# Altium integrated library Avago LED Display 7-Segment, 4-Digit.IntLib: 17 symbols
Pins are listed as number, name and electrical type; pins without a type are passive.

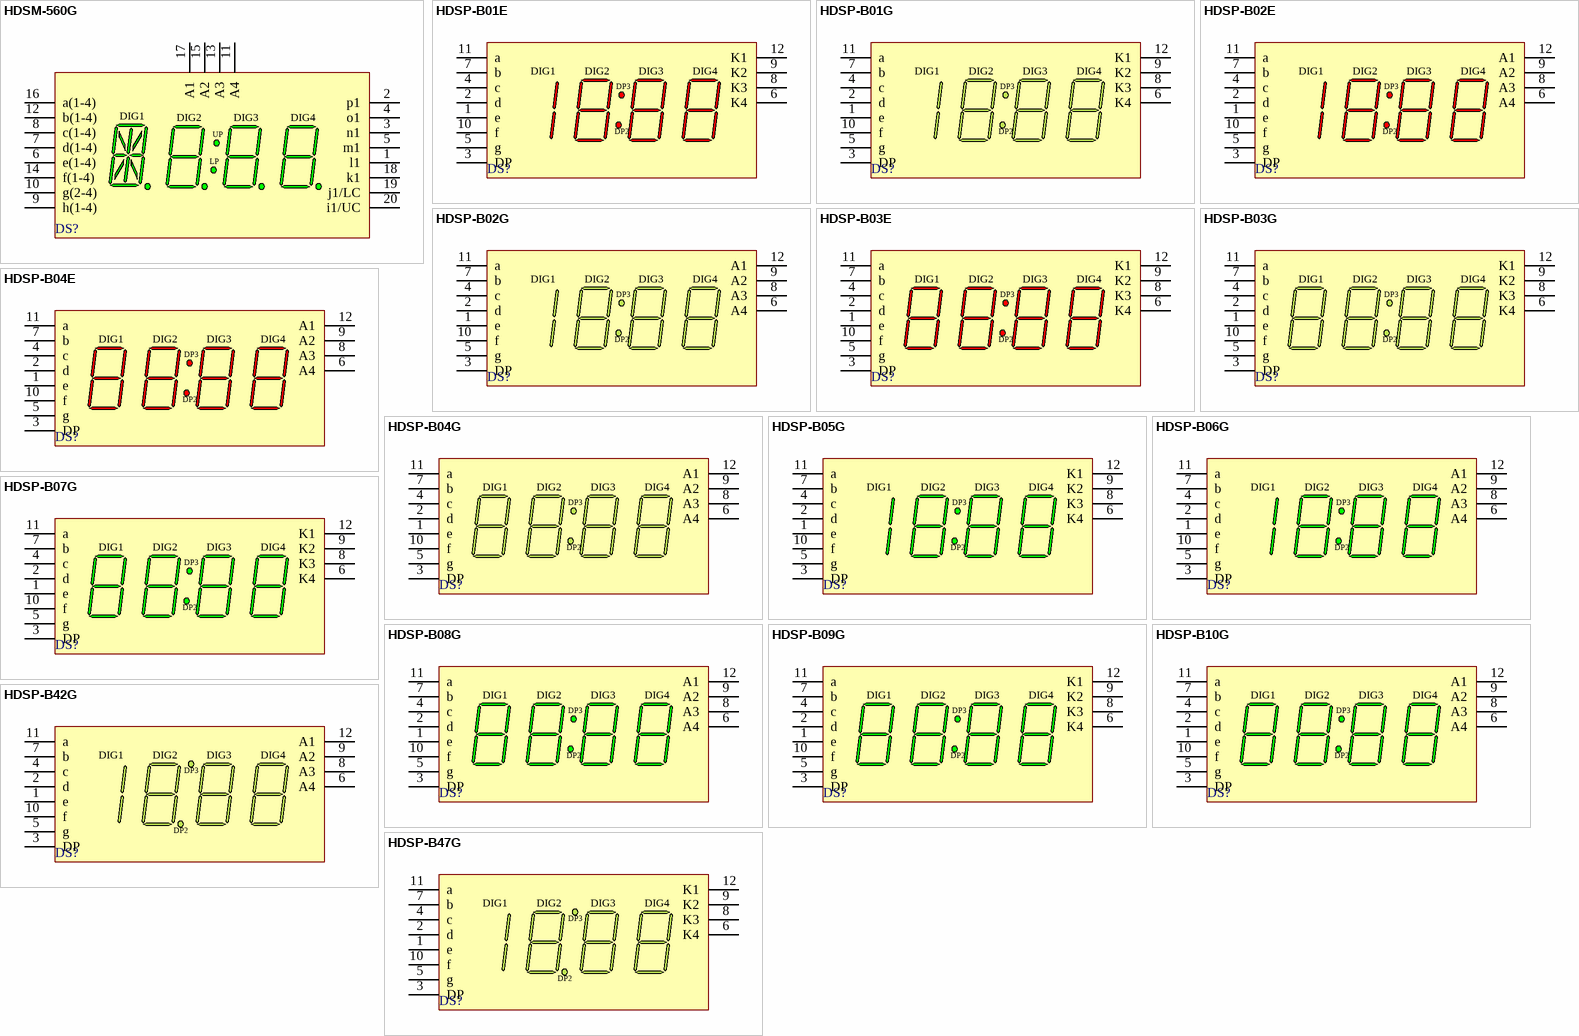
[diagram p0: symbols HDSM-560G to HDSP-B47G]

## HDSM-560G
designator DS?
8.9 mm Black Suface GAP Green 7-Segment Display: 4-Digit, CA; LuminousIntensity: 1250 ucd (Minimum).
footprint HDSM-560 (LED, 7-Segment Display, 8.9 mm, Four Digit; 20 Leads; Row Space 12 mm; Pitch 2.54 mm)
simulation model HDSM_560G (SUBCKT)
pins: 1 l1 "Digit 1 l Cathode", 2 p1 "Digit 1 p Cathode", 3 n1 "Digit 1 n Cathode", 4 o1 "Digit 1 o Cathode", 5 m1 "Digit 1 m Cathode", 6 e(1-4) "Digits (1-4) e Cathode", 7 d(1-4) "Digits (1-4) d Cathode", 8 c(1-4) "Digits (1-4) c Cathode", 9 h(1-4) "Digits (1-4) DP Cathode", 10 g(2-4) "Digits (2-4) g Cathode", 11 A4 "Digit 4 Common Anode", 12 b(1-4) "Digits (1-4) b Cathode", 13 A3 "Digit 3 Common Anode", 14 f(1-4) "Digits (1-4) f Cathode", 15 A2 "Digit 2 Common Anode", 16 a(1-4) "Digits (1-4) a Cathode", 17 A1 "Digit 1 Common Anode", 18 k1 "Digit 1 k Cathode", 19 j1/LC "Digit 1 j, LC Cathode", 20 i1/UC "Digit 1 i, UC Cathode"

## HDSP-B01E
designator DS?
14.22 mm GaP HER, Untinted, 18:88 4-Digit 7-Segment Display: CC, Gray Surface; LuminousIntensity: 3200 ucd (Minimum).; LED_Colour: High Efficiency Red (HER)
footprint B-18 (LED, 7-Segment Display, 14.22 mm, Four Digit, 18:88; 12 Leads; Row Space 15.24 mm; Pitch 2.54 mm)
simulation model HDSP_B01E (SUBCKT)
pins: 1 e "Digits (2-4) e Anode", 2 d "Digits (2-4) d Anode", 3 DP "Digits (2,3) DP Anode", 4 c "Digits (1-4) c Anode", 5 g "Digits (2-4) g Anode", 6 K4 "Digit 4 Common Cathode", 7 b "Digits (1-4) b Anode", 8 K3 "Digit 3 Common Cathode", 9 K2 "Digit 2 Common Cathode", 10 f "Digits (2-4) f Anode", 11 a "Digits (2-4) a Anode", 12 K1 "Digit 1 Common Cathode"

## HDSP-B01G
designator DS?
14.22 mm Tinted Green, 18:88 4-Digit 7-Segment Display: CC, Gray Surface; LuminousIntensity: 2000 ucd (Minimum).
footprint B-18 (LED, 7-Segment Display, 14.22 mm, Four Digit, 18:88; 12 Leads; Row Space 15.24 mm; Pitch 2.54 mm)
simulation model HDSP_B01G (SUBCKT)
pins: 1 e "Digits (2-4) e Anode", 2 d "Digits (2-4) d Anode", 3 DP "Digits (2,3) DP Anode", 4 c "Digits (1-4) c Anode", 5 g "Digits (2-4) g Anode", 6 K4 "Digit 4 Common Cathode", 7 b "Digits (1-4) b Anode", 8 K3 "Digit 3 Common Cathode", 9 K2 "Digit 2 Common Cathode", 10 f "Digits (2-4) f Anode", 11 a "Digits (2-4) a Anode", 12 K1 "Digit 1 Common Cathode"

## HDSP-B02E
designator DS?
14.22 mm GaP HER, Untinted, 18:88 4-Digit 7-Segment Display: CA, Gray Surface; LuminousIntensity: 3200 ucd (Minimum).; LED_Colour: High Efficiency Red (HER)
footprint B-18 (LED, 7-Segment Display, 14.22 mm, Four Digit, 18:88; 12 Leads; Row Space 15.24 mm; Pitch 2.54 mm)
simulation model HDSP_B02E (SUBCKT)
pins: 1 e "Digits (2-4) e Cathode", 2 d "Digits (2-4) d Cathode", 3 DP "Digits (2,3) DP Cathode", 4 c "Digits (1-4) c Cathode", 5 g "Digits (2-4) g Cathode", 6 A4 "Digit 4 Common Anode", 7 b "Digits (1-4) b Cathode", 8 A3 "Digit 3 Common Anode", 9 A2 "Digit 2 Common Anode", 10 f "Digits (2-4) f Cathode", 11 a "Digits (2-4) a Cathode", 12 A1 "Digit 1 Common Anode"

## HDSP-B02G
designator DS?
14.22 mm Tinted Green, 18:88 4-Digit 7-Segment Display: CA, Gray Surface; LuminousIntensity: 2000 ucd (Minimum).
footprint B-18 (LED, 7-Segment Display, 14.22 mm, Four Digit, 18:88; 12 Leads; Row Space 15.24 mm; Pitch 2.54 mm)
simulation model HDSP_B02G (SUBCKT)
pins: 1 e "Digits (2-4) e Cathode", 2 d "Digits (2-4) d Cathode", 3 DP "Digits (2,3) DP Cathode", 4 c "Digits (1-4) c Cathode", 5 g "Digits (2-4) g Cathode", 6 A4 "Digit 4 Common Anode", 7 b "Digits (1-4) b Cathode", 8 A3 "Digit 3 Common Anode", 9 A2 "Digit 2 Common Anode", 10 f "Digits (2-4) f Cathode", 11 a "Digits (2-4) a Cathode", 12 A1 "Digit 1 Common Anode"

## HDSP-B03E
designator DS?
14.22 mm GaP HER, Untinted, 88:88 4-Digit 7-Segment Display: CC, Gray Surface; LuminousIntensity: 3200 ucd (Minimum).; LED_Colour: High Efficiency Red (HER)
footprint B-88 (LED, 7-Segment Display, 14.22 mm, Four Digit, 88:88; 12 Leads; Row Space 15.24 mm; Pitch 2.54 mm)
simulation model HDSP_B03E (SUBCKT)
pins: 1 e "Digits (1-4) e Anode", 2 d "Digits (1-4) d Anode", 3 DP "Digits (2,3) DP Anode", 4 c "Digits (1-4) c Anode", 5 g "Digits (1-4) g Anode", 6 K4 "Digit 4 Common Cathode", 7 b "Digits (1-4) b Anode", 8 K3 "Digit 3 Common Cathode", 9 K2 "Digit 2 Common Cathode", 10 f "Digits (1-4) f Anode", 11 a "Digits (1-4) a Anode", 12 K1 "Digit 1 Common Cathode"

## HDSP-B03G
designator DS?
14.22 mm Tinted Green, 88:88 4-Digit 7-Segment Display: CC, Gray Surface; LuminousIntensity: 2000 ucd (Minimum).
footprint B-88 (LED, 7-Segment Display, 14.22 mm, Four Digit, 88:88; 12 Leads; Row Space 15.24 mm; Pitch 2.54 mm)
simulation model HDSP_B03G (SUBCKT)
pins: 1 e "Digits (1-4) e Anode", 2 d "Digits (1-4) d Anode", 3 DP "Digits (2,3) DP Anode", 4 c "Digits (1-4) c Anode", 5 g "Digits (1-4) g Anode", 6 K4 "Digit 4 Common Cathode", 7 b "Digits (1-4) b Anode", 8 K3 "Digit 3 Common Cathode", 9 K2 "Digit 2 Common Cathode", 10 f "Digits (1-4) f Anode", 11 a "Digits (1-4) a Anode", 12 K1 "Digit 1 Common Cathode"

## HDSP-B04E
designator DS?
14.22 mm GaP HER, Untinted, 88:88 4-Digit 7-Segment Display: CA, Gray Surface; LuminousIntensity: 3200 ucd (Minimum).; LED_Colour: High Efficiency Red (HER)
footprint B-88 (LED, 7-Segment Display, 14.22 mm, Four Digit, 88:88; 12 Leads; Row Space 15.24 mm; Pitch 2.54 mm)
simulation model HDSP_B04E (SUBCKT)
pins: 1 e "Digits (1-4) e Cathode", 2 d "Digits (1-4) d Cathode", 3 DP "Digits (2,3) DP Cathode", 4 c "Digits (1-4) c Cathode", 5 g "Digits (1-4) g Cathode", 6 A4 "Digit 4 Common Anode", 7 b "Digits (1-4) b Cathode", 8 A3 "Digit 3 Common Anode", 9 A2 "Digit 2 Common Anode", 10 f "Digits (1-4) f Cathode", 11 a "Digits (1-4) a Cathode", 12 A1 "Digit 1 Common Anode"

## HDSP-B04G
designator DS?
14.22 mm Tinted Green, 88:88 4-Digit 7-Segment Display: CA, Gray Surface; LuminousIntensity: 2000 ucd (Minimum).
footprint B-88 (LED, 7-Segment Display, 14.22 mm, Four Digit, 88:88; 12 Leads; Row Space 15.24 mm; Pitch 2.54 mm)
simulation model HDSP_B04G (SUBCKT)
pins: 1 e "Digits (1-4) e Cathode", 2 d "Digits (1-4) d Cathode", 3 DP "Digits (2,3) DP Cathode", 4 c "Digits (1-4) c Cathode", 5 g "Digits (1-4) g Cathode", 6 A4 "Digit 4 Common Anode", 7 b "Digits (1-4) b Cathode", 8 A3 "Digit 3 Common Anode", 9 A2 "Digit 2 Common Anode", 10 f "Digits (1-4) f Cathode", 11 a "Digits (1-4) a Cathode", 12 A1 "Digit 1 Common Anode"

## HDSP-B05G
designator DS?
14.22 mm Untinted, 18:88 4-Digit 7-Segment Display: CC, Gray Surface; LuminousIntensity: 3200 ucd (Minimum).; LED_Colour: Green
footprint B-18 (LED, 7-Segment Display, 14.22 mm, Four Digit, 18:88; 12 Leads; Row Space 15.24 mm; Pitch 2.54 mm)
simulation model HDSP_B01G (SUBCKT)
pins: 1 e "Digits (2-4) e Anode", 2 d "Digits (2-4) d Anode", 3 DP "Digits (2,3) DP Anode", 4 c "Digits (1-4) c Anode", 5 g "Digits (2-4) g Anode", 6 K4 "Digit 4 Common Cathode", 7 b "Digits (1-4) b Anode", 8 K3 "Digit 3 Common Cathode", 9 K2 "Digit 2 Common Cathode", 10 f "Digits (2-4) f Anode", 11 a "Digits (2-4) a Anode", 12 K1 "Digit 1 Common Cathode"

## HDSP-B06G
designator DS?
14.22 mm Untinted, 18:88 4-Digit 7-Segment Display: CA, Gray Surface; LuminousIntensity: 3200 ucd (Minimum).; LED_Colour: Green
footprint B-18 (LED, 7-Segment Display, 14.22 mm, Four Digit, 18:88; 12 Leads; Row Space 15.24 mm; Pitch 2.54 mm)
simulation model HDSP_B02G (SUBCKT)
pins: 1 e "Digits (2-4) e Cathode", 2 d "Digits (2-4) d Cathode", 3 DP "Digits (2,3) DP Cathode", 4 c "Digits (1-4) c Cathode", 5 g "Digits (2-4) g Cathode", 6 A4 "Digit 4 Common Anode", 7 b "Digits (1-4) b Cathode", 8 A3 "Digit 3 Common Anode", 9 A2 "Digit 2 Common Anode", 10 f "Digits (2-4) f Cathode", 11 a "Digits (2-4) a Cathode", 12 A1 "Digit 1 Common Anode"

## HDSP-B07G
designator DS?
14.22 mm Untinted, 88:88 4-Digit 7-Segment Display: CC, Gray Surface; LuminousIntensity: 3200 ucd (Minimum).; LED_Colour: Green
footprint B-88 (LED, 7-Segment Display, 14.22 mm, Four Digit, 88:88; 12 Leads; Row Space 15.24 mm; Pitch 2.54 mm)
simulation model HDSP_B03G (SUBCKT)
pins: 1 e "Digits (1-4) e Anode", 2 d "Digits (1-4) d Anode", 3 DP "Digits (2,3) DP Anode", 4 c "Digits (1-4) c Anode", 5 g "Digits (1-4) g Anode", 6 K4 "Digit 4 Common Cathode", 7 b "Digits (1-4) b Anode", 8 K3 "Digit 3 Common Cathode", 9 K2 "Digit 2 Common Cathode", 10 f "Digits (1-4) f Anode", 11 a "Digits (1-4) a Anode", 12 K1 "Digit 1 Common Cathode"

## HDSP-B08G
designator DS?
14.22 mm Untinted, 88:88 4-Digit 7-Segment Display: CA, Gray Surface; LuminousIntensity: 3200 ucd (Minimum).; LED_Colour: Green
footprint B-88 (LED, 7-Segment Display, 14.22 mm, Four Digit, 88:88; 12 Leads; Row Space 15.24 mm; Pitch 2.54 mm)
simulation model HDSP_B04G (SUBCKT)
pins: 1 e "Digits (1-4) e Cathode", 2 d "Digits (1-4) d Cathode", 3 DP "Digits (2,3) DP Cathode", 4 c "Digits (1-4) c Cathode", 5 g "Digits (1-4) g Cathode", 6 A4 "Digit 4 Common Anode", 7 b "Digits (1-4) b Cathode", 8 A3 "Digit 3 Common Anode", 9 A2 "Digit 2 Common Anode", 10 f "Digits (1-4) f Cathode", 11 a "Digits (1-4) a Cathode", 12 A1 "Digit 1 Common Anode"

## HDSP-B09G
designator DS?
14.22 mm Untinted, 88:88 4-Digit 7-Segment Display: CC, Black Surface; LuminousIntensity: 3200 ucd (Minimum).; LED_Colour: Green
footprint B-88 (LED, 7-Segment Display, 14.22 mm, Four Digit, 88:88; 12 Leads; Row Space 15.24 mm; Pitch 2.54 mm)
simulation model HDSP_B03G (SUBCKT)
pins: 1 e "Digits (1-4) e Anode", 2 d "Digits (1-4) d Anode", 3 DP "Digits (2,3) DP Anode", 4 c "Digits (1-4) c Anode", 5 g "Digits (1-4) g Anode", 6 K4 "Digit 4 Common Cathode", 7 b "Digits (1-4) b Anode", 8 K3 "Digit 3 Common Cathode", 9 K2 "Digit 2 Common Cathode", 10 f "Digits (1-4) f Anode", 11 a "Digits (1-4) a Anode", 12 K1 "Digit 1 Common Cathode"

## HDSP-B10G
designator DS?
14.22 mm Untinted, 88:88 4-Digit 7-Segment Display: CA, Black Surface; LuminousIntensity: 3200 ucd (Minimum).; LED_Colour: Green
footprint B-88 (LED, 7-Segment Display, 14.22 mm, Four Digit, 88:88; 12 Leads; Row Space 15.24 mm; Pitch 2.54 mm)
simulation model HDSP_B04G (SUBCKT)
pins: 1 e "Digits (1-4) e Cathode", 2 d "Digits (1-4) d Cathode", 3 DP "Digits (2,3) DP Cathode", 4 c "Digits (1-4) c Cathode", 5 g "Digits (1-4) g Cathode", 6 A4 "Digit 4 Common Anode", 7 b "Digits (1-4) b Cathode", 8 A3 "Digit 3 Common Anode", 9 A2 "Digit 2 Common Anode", 10 f "Digits (1-4) f Cathode", 11 a "Digits (1-4) a Cathode", 12 A1 "Digit 1 Common Anode"

## HDSP-B42G
designator DS?
14.22 mm Tinted Green, 18:88 4-Digit 7-Segment Display: CA, Neutral Gray Surface; LuminousIntensity: 2000 ucd (Minimum).
footprint HDSP-B4 (LED, 7-Segment Display, 14.22 mm, Four Digit, 18:88; 12 Leads; Row Space 15.24 mm; Pitch 2.54 mm)
simulation model HDSP_B42G (SUBCKT)
pins: 1 e "Digits (2-4) e Cathode", 2 d "Digits (2-4) d Cathode", 3 DP "Digits (2,3) DP Cathode", 4 c "Digits (1-4) c Cathode", 5 g "Digits (2-4) g Cathode", 6 A4 "Digit 4 Common Anode", 7 b "Digits (1-4) b Cathode", 8 A3 "Digit 3 Common Anode", 9 A2 "Digit 2 Common Anode", 10 f "Digits (2-4) f Cathode", 11 a "Digits (2-4) a Cathode", 12 A1 "Digit 1 Common Anode"

## HDSP-B47G
designator DS?
14.22 mm Tinted Green, 18:88 4-Digit 7-Segment Display: CC, Neutral Gray Surface; LuminousIntensity: 2000 ucd (Minimum).
footprint HDSP-B4 (LED, 7-Segment Display, 14.22 mm, Four Digit, 18:88; 12 Leads; Row Space 15.24 mm; Pitch 2.54 mm)
simulation model HDSP_B47G (SUBCKT)
pins: 1 e "Digits (2-4) e Anode", 2 d "Digits (2-4) d Anode", 3 DP "Digits (2,3) DP Anode", 4 c "Digits (1-4) c Anode", 5 g "Digits (2-4) g Anode", 6 K4 "Digit 4 Common Cathode", 7 b "Digits (1-4) b Anode", 8 K3 "Digit 3 Common Cathode", 9 K2 "Digit 2 Common Cathode", 10 f "Digits (2-4) f Anode", 11 a "Digits (2-4) a Anode", 12 K1 "Digit 1 Common Cathode"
